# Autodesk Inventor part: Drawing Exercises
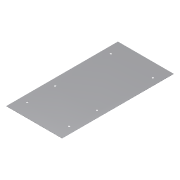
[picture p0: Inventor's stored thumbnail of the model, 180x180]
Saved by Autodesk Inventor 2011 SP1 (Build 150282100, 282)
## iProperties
Created: 2011-02
Part Number: Drawing Exercises
Document SubType Name: Sheet Metal
Designer: SERGIO
Density: 1 g/cm^3
Sheet Metal Rule: Default
Author: SERGIO
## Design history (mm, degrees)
node "Face1"
  sketch "Sketch1"
    geometry: L1 (-100, 200)-(100, 200); L2 (100, 200)-(100, -200); L3 (100, -200)-(-100, -200); L4 (-100, -200)-(-100, 200); 3 further points
    constraints: 8 end point, 2 midpoint, 2 parallel, 1 horizontal, 1 horizontal alignment, 1 perpendicular, 1 vertical alignment
    dimensions: "d0" = 200 distance of L2.end L3.end; "d1" = 400 distance of L1.end L2.end
sketch "Sketch2"
  geometry: L1 (100, -200)-(-100, -200) reference; L2 (0, -280)-(0, 280) reference; 7 further points
  constraints: 4 vertical alignment, 3 symmetric about line
  dimensions: "d3" = 150 distance of point (75, 150) point (-75, 150); "d4" = 200 distance of point (-75, -50) point (-75, 150); "d5" = 100 distance of point (-75, -150) point (-75, -50); "d6" = 50 distance from line of L1 point (-75, -150)
hole "Hole1" sketch "Sketch2" at (-75, -150), (-75, -50), (-75, 150), (75, -150), (75, -50), (75, 150) diameter "d7" = 6; stored, may be unused: countersink angle "d11" = 90 deg, drill point angle "d13" = 118 deg; dims "d8" = 6, "d9" = 4, "d10" = 2, "d12" = 0.5 (= Thickness)
body "Solid1"
face "Plate1" dims "Thickness" = 0.5
other parameters: "KFactor" = 4.4, "BendRadius" = 0.5 (= Thickness), "BendReliefWidth" = 0.5 (= Thickness), "BendReliefDepth" = 0.25 (= 0.5 x Thickness), "CornerReliefSize" = 2 (= 4 x Thickness), "SeamGap" = 0.01, "MinimumRemnant" = 1 (= 2 x Thickness), "TransitionRadius" = 0.5 (= BendRadius), "JacobiRadiusSize" = 0.5 (= Thickness), "GapSize" = 0.5 (= Thickness), "d2" = 0.5 (= BendRadius)
